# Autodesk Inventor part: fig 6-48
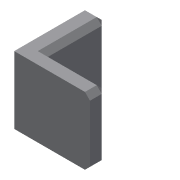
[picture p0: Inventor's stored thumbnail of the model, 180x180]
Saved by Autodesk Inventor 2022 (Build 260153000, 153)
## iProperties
Created: 2009-09
Part Number: fig 6-48
Document SubType Name: Modeling
Designer: Sham
Density: 1 g/cm^3
Material: Generic
Appearance: Default
Author: Sham
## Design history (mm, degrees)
sketch "Sketch1"
  geometry: L1 (1.789, 30)-(1.789, -5); L2 (1.789, -5)-(36.789, -5); L3 (36.789, -5)-(36.789, -15); L4 (36.789, -15)-(-8.211, -15); L5 (-8.211, -15)-(-8.211, 30); L6 (-8.211, 30)-(1.789, 30)
  constraints: 12 end point, 6 perpendicular
  dimensions: "d0" = 10 distance of L5.end L1.start; "d1" = 35 distance of L1.start L1.end; "d2" = 45 distance of L3.end L4.end; "d3" = 10 distance of L2.end L3.end (derived)
extrude "Extrusion1" new body sketch "Sketch1" distance "d4" = 40; taper "d5" = 0 deg
chamfer "Chamfer1" distance "d6" = 3; stored, may be unused: second distance "d7" = 2, angle "d8" = 45 deg
body "Solid1"
other parameters: "d1" = 35
